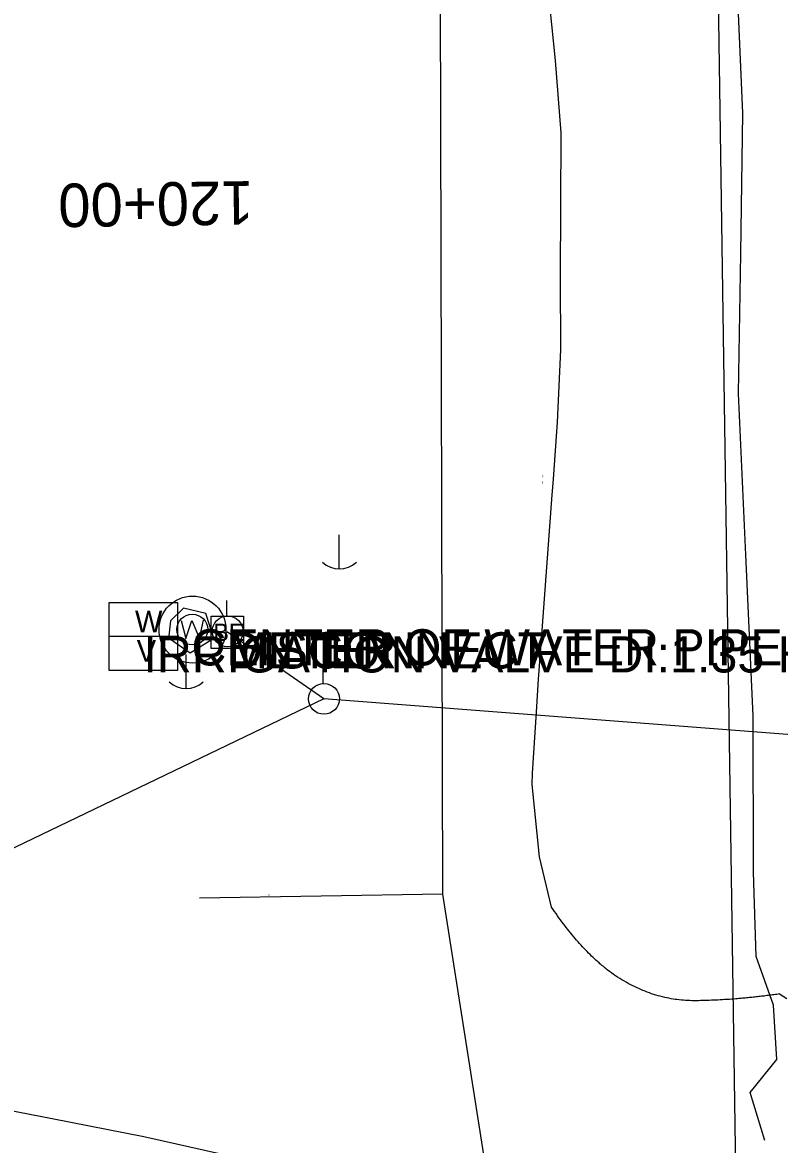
# Model space of a CAD drawing. Extents: x 1674300 to 1677920, y 225056 to 231852.
# Drawn here: x 1677236.4 to 1677341.1, y 229147 to 229302.1 of the extents above; entities that cross this region are included whole.
import ezdxf

# ---------------------------------------------------------------- set-up
doc = ezdxf.new("R2010")
doc.units = 0
for name, color, linetype in [('R_Annotation', 7, 'Continuous'), ('R_Horz Alg Annot', 7, 'Continuous'), ('R_Proposed Const Limits_Cut', 7, 'Continuous'), ('R_ROW', 7, 'Continuous'), ('R_ROW Annot', 7, 'Continuous'), ('S_DITCHLINE', 7, 'Continuous'), ('S_EDGE_CONCRETE', 7, 'Continuous'), ('S_ELECTRIC_UTILITIES', 7, 'Continuous'), ('S_ELECTRIC_UTILITIES_ANNOT', 7, 'Continuous'), ('S_EXIST_ROW', 7, 'Continuous'), ('S_STREAM', 7, 'Continuous'), ('S_UTILITY_POLE', 7, 'Continuous'), ('S_UTL_PT_SYM', 7, 'Continuous'), ('S_WATER_UTILITIES', 7, 'Continuous'), ('S_WATER_UTILITIES_ANNOT', 7, 'Continuous'), ('S_WATER_WELL_ANNOT', 7, 'Continuous')]:
    doc.layers.add(name, color=color, linetype=linetype)

msp = doc.modelspace()

# ---------------------------------------------------------------- linework, layer by layer
at = {"layer": 'R_Proposed Const Limits_Cut'}
for points in [[(1677309.61, 229179.84), (1677307.95, 229186.81), (1677306.92, 229196.8), (1677306.95, 229198.35), (1677307.5, 229206.81), (1677307.81, 229211.36), (1677308.19, 229216.82), (1677308.94, 229226.83), (1677309.7, 229236.84), (1677309.86, 229239), (1677310.43, 229246.85), (1677310.9, 229256.86), (1677310.85, 229266.86), (1677310.89, 229276.86), (1677310.95, 229286.87), (1677310.13, 229296.86), (1677309.11, 229306.84)], [(1677341.12, 229167.85), (1677342.13, 229167.24)]]:
    msp.add_lwpolyline(points, dxfattribs=at)
msp.add_open_spline([(1677341.12, 229167.85), (1677334.96, 229166.98), (1677324.18, 229166.86), (1677314.33, 229172.85), (1677309.61, 229179.84)], degree=2, dxfattribs=at)
at = {"layer": 'R_ROW'}
msp.add_line((1677294.58, 229181.63), (1677293.32, 229626.65), dxfattribs=at)
msp.add_lwpolyline([(1677280.82, 228594.47), (1677312.38, 228785.76), (1677312.38, 228785.76), (1677316.54, 229041.92), (1677294.58, 229181.63), (1677294.58, 229181.63)], dxfattribs=at)
at = {"layer": 'R_ROW Annot'}
msp.add_line((1677294.58, 229181.63), (1677260.94, 229181.07), dxfattribs=at)
at = {"layer": 'S_DITCHLINE'}
msp.add_lwpolyline([(1677339.09, 229147.6), (1677337.05, 229154.23), (1677340.76, 229158.8), (1677340.29, 229166.32), (1677337.9, 229173.01), (1677337.54, 229184.7), (1677337.47, 229206.29), (1677336.46, 229228.55), (1677335.46, 229250.81), (1677335.75, 229270.19), (1677336.05, 229289.58), (1677334.99, 229313.98), (1677333.93, 229338.37), (1677333.99, 229360.23), (1677334.04, 229382.08), (1677334.5, 229402.19), (1677334.96, 229422.29), (1677334.69, 229446.15), (1677334.41, 229470.02), (1677334.41, 229473.73)], dxfattribs=at)
at = {"layer": 'S_EDGE_CONCRETE'}
msp.add_lwpolyline([(1677256.8, 229216.96), (1677259.63, 229214.99), (1677262.93, 229217), (1677261.81, 229220.41), (1677258.73, 229221.18), (1677256.93, 229219.41), (1677256.67, 229217.35)], close=True, dxfattribs=at)
at = {"layer": 'S_ELECTRIC_UTILITIES'}
for p, q in [((1677278.13, 229208.63), (1677264.79, 229217.83)), ((1677278.13, 229208.63), (1677031.23, 229090)), ((1677541.68, 229188.35), (1677278.13, 229208.63))]:
    msp.add_line(p, q, dxfattribs=at)
for points in [[(1677262.52, 229215.58), (1677262.52, 229220.08), (1677267.02, 229220.08), (1677267.02, 229215.58)], [(1677262.53, 229215.58), (1677262.53, 229220.08), (1677267.03, 229220.08), (1677267.03, 229215.58)]]:
    msp.add_lwpolyline(points, close=True, dxfattribs=at)
at = {"layer": 'S_EXIST_ROW'}
msp.add_line((1677337.07, 229010.49), (1677299.88, 231497.46), dxfattribs=at)
at = {"layer": 'S_STREAM'}
msp.add_lwpolyline([(1677274.96, 229143.23), (1677253.24, 229148.13), (1677240.58, 229150.59), (1677227.91, 229153.05), (1677211.81, 229151.5), (1677195.72, 229149.95), (1677183.04, 229148.43), (1677170.36, 229146.92)], dxfattribs=at)
at = {"layer": 'S_UTILITY_POLE'}
for p, q in [((1677280.21, 229231.29), (1677280.21, 229226.56)), ((1677264.7, 229220.1), (1677264.7, 229222.21)), ((1677259.03, 229214.76), (1677259.03, 229210.03)), ((1677278.01, 229210.77), (1677278.01, 229212.88))]:
    msp.add_line(p, q, dxfattribs=at)
for centre in [(1677264.82, 229217.96), (1677278.13, 229208.63)]:
    msp.add_circle(centre, 2.13, dxfattribs=at)
for centre in [(1677280.27, 229229.99), (1677259.09, 229213.46)]:
    msp.add_arc(centre, 3.41, 226.3972, 313.6028, dxfattribs=at)
at = {"layer": 'S_UTL_PT_SYM'}
for points in [[(1677264.79, 229217.83), (1677264.79, 229217.88), (1677264.79, 229217.83), (1677264.74, 229217.83), (1677264.79, 229217.83), (1677264.79, 229217.78), (1677264.79, 229217.83), (1677264.84, 229217.83)], [(1677278.13, 229208.63), (1677278.13, 229208.68), (1677278.13, 229208.63), (1677278.08, 229208.63), (1677278.13, 229208.63), (1677278.13, 229208.58), (1677278.13, 229208.63), (1677278.18, 229208.63)], [(1677278.13, 229208.63), (1677278.13, 229208.68), (1677278.13, 229208.63), (1677278.08, 229208.63), (1677278.13, 229208.63), (1677278.13, 229208.58), (1677278.13, 229208.63), (1677278.18, 229208.63)]]:
    msp.add_lwpolyline(points, dxfattribs=at)
at = {"layer": 'S_WATER_UTILITIES'}
for p, q in [((1677248.46, 229221.97), (1677257.88, 229221.97)), ((1677248.46, 229212.56), (1677248.46, 229221.97)), ((1677257.88, 229221.97), (1677257.88, 229212.56)), ((1677258.4, 229219.47), (1677259.06, 229216.99)), ((1677259.06, 229216.99), (1677259.87, 229219.47)), ((1677259.87, 229219.47), (1677260.92, 229216.99)), ((1677260.92, 229216.99), (1677261.5, 229219.51)), ((1677248.46, 229217.28), (1677257.88, 229217.28)), ((1677257.88, 229212.56), (1677248.46, 229212.56))]:
    msp.add_line(p, q, dxfattribs=at)
for centre, radius in [((1677259.96, 229218.21), 4.63), ((1677259.93, 229218.21), 2.13)]:
    msp.add_circle(centre, radius, dxfattribs=at)

# ---------------------------------------------------------------- texts
at = {"layer": 'R_Annotation'}
msp.add_text('CONST. LIMITS', height=0.12, rotation=87.1086, dxfattribs=at).set_placement((1677308.4, 229238.31))
at = {"layer": 'R_Horz Alg Annot'}
msp.add_text('120+00', height=6, rotation=180.8056, dxfattribs=at).set_placement((1677268.35, 229280.19))
at = {"layer": 'R_ROW Annot'}
for s, p in [('+05', (1677270.65, 229181.51)), ("80'", (1677270.62, 229181.69))]:
    msp.add_text(s, height=0.12, rotation=180.9497, dxfattribs=at).set_placement(p)
at = {"layer": 'S_ELECTRIC_UTILITIES'}
for p in [(1677262.84, 229216.63), (1677262.85, 229216.63)]:
    msp.add_text('BE', height=2.4, rotation=360, dxfattribs=at).set_placement(p)
at = {"layer": 'S_ELECTRIC_UTILITIES_ANNOT'}
for s, p in [('DISCONNECT', (1677264.79, 229212.83)), ('METER', (1677264.8, 229212.83))]:
    msp.add_text(s, height=5, rotation=360, dxfattribs=at).set_placement(p)
at = {"layer": 'S_WATER_UTILITIES'}
for s, p in [('W', (1677252.01, 229217.81)), ('V', (1677252.25, 229213.75))]:
    msp.add_text(s, height=3, rotation=360, dxfattribs=at).set_placement(p)
at = {"layer": 'S_WATER_UTILITIES_ANNOT'}
msp.add_text('IRRIGATION VALVE DI:1.35 HT:5.00', height=5, rotation=360, dxfattribs=at).set_placement((1677253.17, 229212.28))
at = {"layer": 'S_WATER_WELL_ANNOT'}
msp.add_text('CENTER OF WATER PIPE', height=5, rotation=360, dxfattribs=at).set_placement((1677259.81, 229213.25))

doc.saveas('drawing.dxf')
